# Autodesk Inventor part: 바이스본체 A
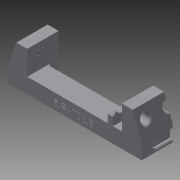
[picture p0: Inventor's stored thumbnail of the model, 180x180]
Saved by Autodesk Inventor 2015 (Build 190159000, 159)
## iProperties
Created: 2017-04
Part Number: 바이스본체 A
Material: 알루미늄 6061
Document SubType Name: Modeling
Designer: mduedu
Density: 2.71 g/cm^3
Appearance: 기본값
Mass: 246.801 g
Surface Area: 212.061 cm^2
Volume: 91.0704 cm^3
Author: mduedu
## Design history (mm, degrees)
sketch "스케치1"
  geometry: L1 (-75, 0)-(75, 0); L2 (-75, 0)-(-75, 17); L3 (-53, 17)-(53, 17); L4 (75, 17)-(75, 0); L5 (-75, 17)-(-65.173, 44); L6 (-65.173, 44)-(-53, 44); L7 (-53, 44)-(-53, 17); L8 (0, 0)-(0, 17); L9 (75, 17)-(65.173, 44); L10 (65.173, 44)-(53, 44); L11 (53, 44)-(53, 17); 1 further point
  constraints: 22 end point, 4 perpendicular, 2 horizontal alignment, 2 midpoint, 2 symmetric about line, 1 coincident, 1 collinear, 1 horizontal, 1 vertical
  dimensions: "d0" = 150 distance of L1.start L1.end; "d1" = 17 distance of L1.start L2.end; "d2" = 27 distance of L3.start L6.end; "d3" = 22 distance of L3.start L2.end; "d4" = 70 deg angle of L3 L5; "d54" = 20 deg angle of L9 L4
extrude "돌출1" new body sketch "스케치1" stored distance "d5" = 70; taper "d6" = 0 deg
sketch "스케치2"
  geometry: L1 (0, 70)-(106, 70) reference; L2 (106, 70)-(106, 0) reference; L3 (106, 0)-(0, 0) reference; L4 (0, 47)-(106, 47); L5 (106, 47)-(106, 23); L6 (106, 23)-(0, 23); L7 (0, 23)-(0, 47); L8 (0, 70)-(0, 0) reference; 2 further points
  constraints: 8 end point, 2 parallel, 2 point on line, 1 horizontal, 1 horizontal alignment, 1 midpoint, 1 perpendicular
  dimensions: "d7" = 24 distance between parallel lines of L6 L4
extrude "돌출2" cut sketch "스케치2" stored distance "d9" = 70; taper "d10" = 0 deg
sketch "스케치3"
  geometry: L1 (22, -23)-(128, -23) reference; L2 (128, -47)-(22, -47) reference; L3 (22, -18)-(128, -18); L4 (128, -52)-(22, -52); L5 (22, -18)-(22, -52); L6 (128, -18)-(128, -52); 1 further point
  constraints: 8 end point, 3 parallel, 2 point on line, 1 perpendicular
  dimensions: "d11" = 5 distance between parallel lines of L3 L1; "d12" = 5 distance between parallel lines of L4 L2
extrude "돌출3" cut sketch "스케치3" distance "d13" = 12; taper "d14" = 0 deg
fillet "모깎기1" dims "d15" = 3, "d16" = 3
sketch "스케치4"
  geometry: L1 (103, 23)-(3, 23) reference; L2 (0, 26)-(0, 0) reference; L3 (106, 0)-(0, 0) reference; L4 (106, 26)-(106, 0) reference; L5 (96, 0)-(90, 0); L6 (90, 0)-(90, 19.5); L7 (96, 19.5)-(96, 0); L8 (90, 19.5)-(96, 19.5); A1 r 3 centre (3, 26) between (0, 26) and (3, 23) reference; A2 r 3 centre (103, 26) between (103, 23) and (106, 26) reference; 1 further point
  constraints: 8 end point, 2 perpendicular, 1 horizontal, 1 parallel, 1 point on line
  dimensions: "d17" = 10 distance between parallel lines of L7 L4; "d18" = 6 distance between parallel lines of L7 L6; "d27" = 3.5 distance between parallel lines of L8 L1
extrude "돌출4" join sketch "스케치4" distance "d19" = 12; taper "d20" = 0 deg
chamfer "모따기1" distance "d21" = 3; stored, may be unused: second distance "d22" = 2, angle "d23" = 45 deg
chamfer "모따기2" distance "d24" = 3; stored, may be unused: second distance "d25" = 2, angle "d26" = 45 deg
sketch "스케치5"
  geometry: L1 (-15.5, 35.8)-(-15.5, -25.8) reference; L2 (19.5, 0)-(0, 0) reference; C1 r 6.5 at (9.5, 15); 1 further point
  constraints: 1 centre point
  dimensions: "d28" = 13 diameter of C1; "d30" = 15 distance from line of C1.centre L2; "d31" = 25 distance from line of C1.centre L1
extrude "돌출5" cut sketch "스케치5" stored distance "d32" = 12; taper "d33" = 0 deg
sketch "스케치6"
  geometry: C1 r 5 at (-10, 15); C2 r 5 at (-60, 15); A1 r 6.5 centre (-10, 15) between (-15.766, 12) and (-4.234, 12) reference; A2 r 6.5 centre (-60, 15) between (-65.766, 12) and (-54.234, 12) reference; 1 further point
  constraints: 2 centre point, 2 coincident
  dimensions: "d34" = 10 diameter of C1; "d35" = 10 diameter of C2 (= d34)
extrude "돌출6" cut sketch "스케치6" stored distance "d36" = 12; taper "d37" = 0 deg
chamfer "모따기3" distance "d38" = 1; stored, may be unused: second distance "d39" = 2, angle "d40" = 45 deg
chamfer "모따기4" distance "d41" = 1; stored, may be unused: second distance "d42" = 2, angle "d43" = 45 deg
sketch "스케치7"
  geometry: L1 (-35, 35.8)-(-35, -25.8) reference; L2 (-70, 0)-(0, 0) reference; C1 r 5 at (-35, 15); 1 further point
  constraints: 1 centre point, 1 point on line
  dimensions: "d44" = 10 diameter of C1; "d45" = 15 distance from line of C1.centre L2
extrude "돌출7" cut sketch "스케치7" stored distance "d46" = 12; taper "d47" = 0 deg
chamfer "모따기5" distance "d48" = 1; stored, may be unused: second distance "d49" = 2, angle "d50" = 45 deg
node "작업축1"
sketch "스케치8"
  geometry: L1 (-105, 32)-(105, 32) reference; L2 (58, 32)-(64, 32); L3 (64, 32)-(64, 40); L4 (64, 40)-(58, 40); L5 (58, 40)-(58, 32); L6 (53, 38)-(53, 26) reference; 1 further point
  constraints: 8 end point, 2 parallel, 1 horizontal, 1 perpendicular, 1 point on line
  dimensions: "d51" = 5 distance from line of L6 L2.start; "d52" = 6 distance of L3.end L4.end; "d53" = 16 diameter of L4 L1
revolve "회전1" sketch "스케치8" stored, may be unused: angle "d55" = 90 deg
fillet "모깎기2"
chamfer "모따기6" distance "d56" = 1; stored, may be unused: second distance "d57" = 2, angle "d58" = 45 deg
sketch "스케치9"
  geometry: L1 (17.5, 3)-(52.5, 3); L2 (52.5, 13)-(17.5, 13); L3 (70, 0)-(0, 0) reference; L4 (17.5, 8)-(52.5, 8); A1 r 5 centre (17.5, 8) between (17.5, 13) and (17.5, 3); A2 r 5 centre (52.5, 8) between (52.5, 3) and (52.5, 13); 3 further points
  constraints: 6 end point, 4 point on circle, 3 tangent, 2 centre point, 2 midpoint, 2 parallel, 1 horizontal, 1 vertical alignment
  dimensions: "d59" = 35 distance of L4.start L4.end; "d61" = 5 radius of A2; "d62" = 8 distance between parallel lines of L3 L4
extrude "돌출8" cut sketch "스케치9" distance "d63" = 3; taper "d64" = 0 deg
chamfer "모따기7" distance "d65" = 1; stored, may be unused: second distance "d66" = 2, angle "d67" = 45 deg
chamfer "모따기8" distance "d68" = 1; stored, may be unused: second distance "d69" = 2, angle "d70" = 45 deg
feature "분할1"
sketch "스케치10"
  geometry: L1 (35, 27)-(0, 27) reference; L2 (0, 0)-(0, 27) reference; 1 further point
  dimensions: "d85" = 11.5 distance from line of point (12, 15.5) L1; "d86" = 12 distance from line of point (12, 15.5) L2
hole "구멍1" sketch "스케치10" at (12, 15.5) diameter "d71" = 3.242; stored, may be unused: countersink angle "d75" = 90 deg, drill point angle "d77" = 120 deg; dims "d72" = 6, "d73" = 4, "d74" = 2, "d76" = 8
sketch "스케치11"
  geometry: A1 r 5 centre (17.5, 8) between (17.5, 13) and (17.5, 3) reference; 1 further point
  constraints: 1 coincident
hole "구멍3" sketch "스케치11" at (17.5, 8) diameter "d78" = 2.459; stored, may be unused: countersink angle "d82" = 90 deg, drill point angle "d84" = 120 deg; dims "d79" = 4.5, "d80" = 4, "d81" = 2, "d83" = 6
sketch "스케치12"
  geometry: L1 (-75, 0)-(75, 0) reference; 3 further points
  constraints: 1 midpoint, 1 vertical alignment, 1 other
  dimensions: "d87" = 8 distance of point (0, 8) point (0, 0)
feature "엠보싱1" sketch "스케치12" dims "d7" = 24, "d88" = 0.5, "d89" = 0
node "솔리드1"
mirror "대칭1"
mirror "대칭2"
mirror "대칭3"
mirror "대칭4"
node "투영된 루프1"
